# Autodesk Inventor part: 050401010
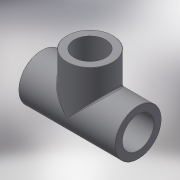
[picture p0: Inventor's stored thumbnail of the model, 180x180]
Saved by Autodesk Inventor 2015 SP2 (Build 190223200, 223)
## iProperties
Created: 2017-10
Part Number: 050401010
Material: Generic
Description: PLASSON THREADED TEE PVC 1"
Document SubType Name: Modeling
Designer: KIM
Density: 1 g/cm^3
Appearance: Default
Author: KIM
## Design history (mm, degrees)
derived "050401.ipt"
feature "Solid1::050401.ipt"
feature "Solid2::050401.ipt"
tag "TaggingFeature1"
body "Solid1"
other parameters: "d0" = 78, "d1" = 42, "d2" = 24, "d4" = 30.291, "d5" = 27.2619, "d7" = 0.30291, "d8" = 24, "d9" = 39, "d10" = 42, "d15" = 0, "d18" = 30.291, "d24" = 0.30291, "d30" = 30.291, "d31" = 24, "d32" = 0, "d33" = 27.2619, "d35" = 0, "d36" = 1.51455, "G_" = 30.291, "E_" = 42, "H_" = 78, "lt_" = 24
